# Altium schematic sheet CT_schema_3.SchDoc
size 335 x 238 mm
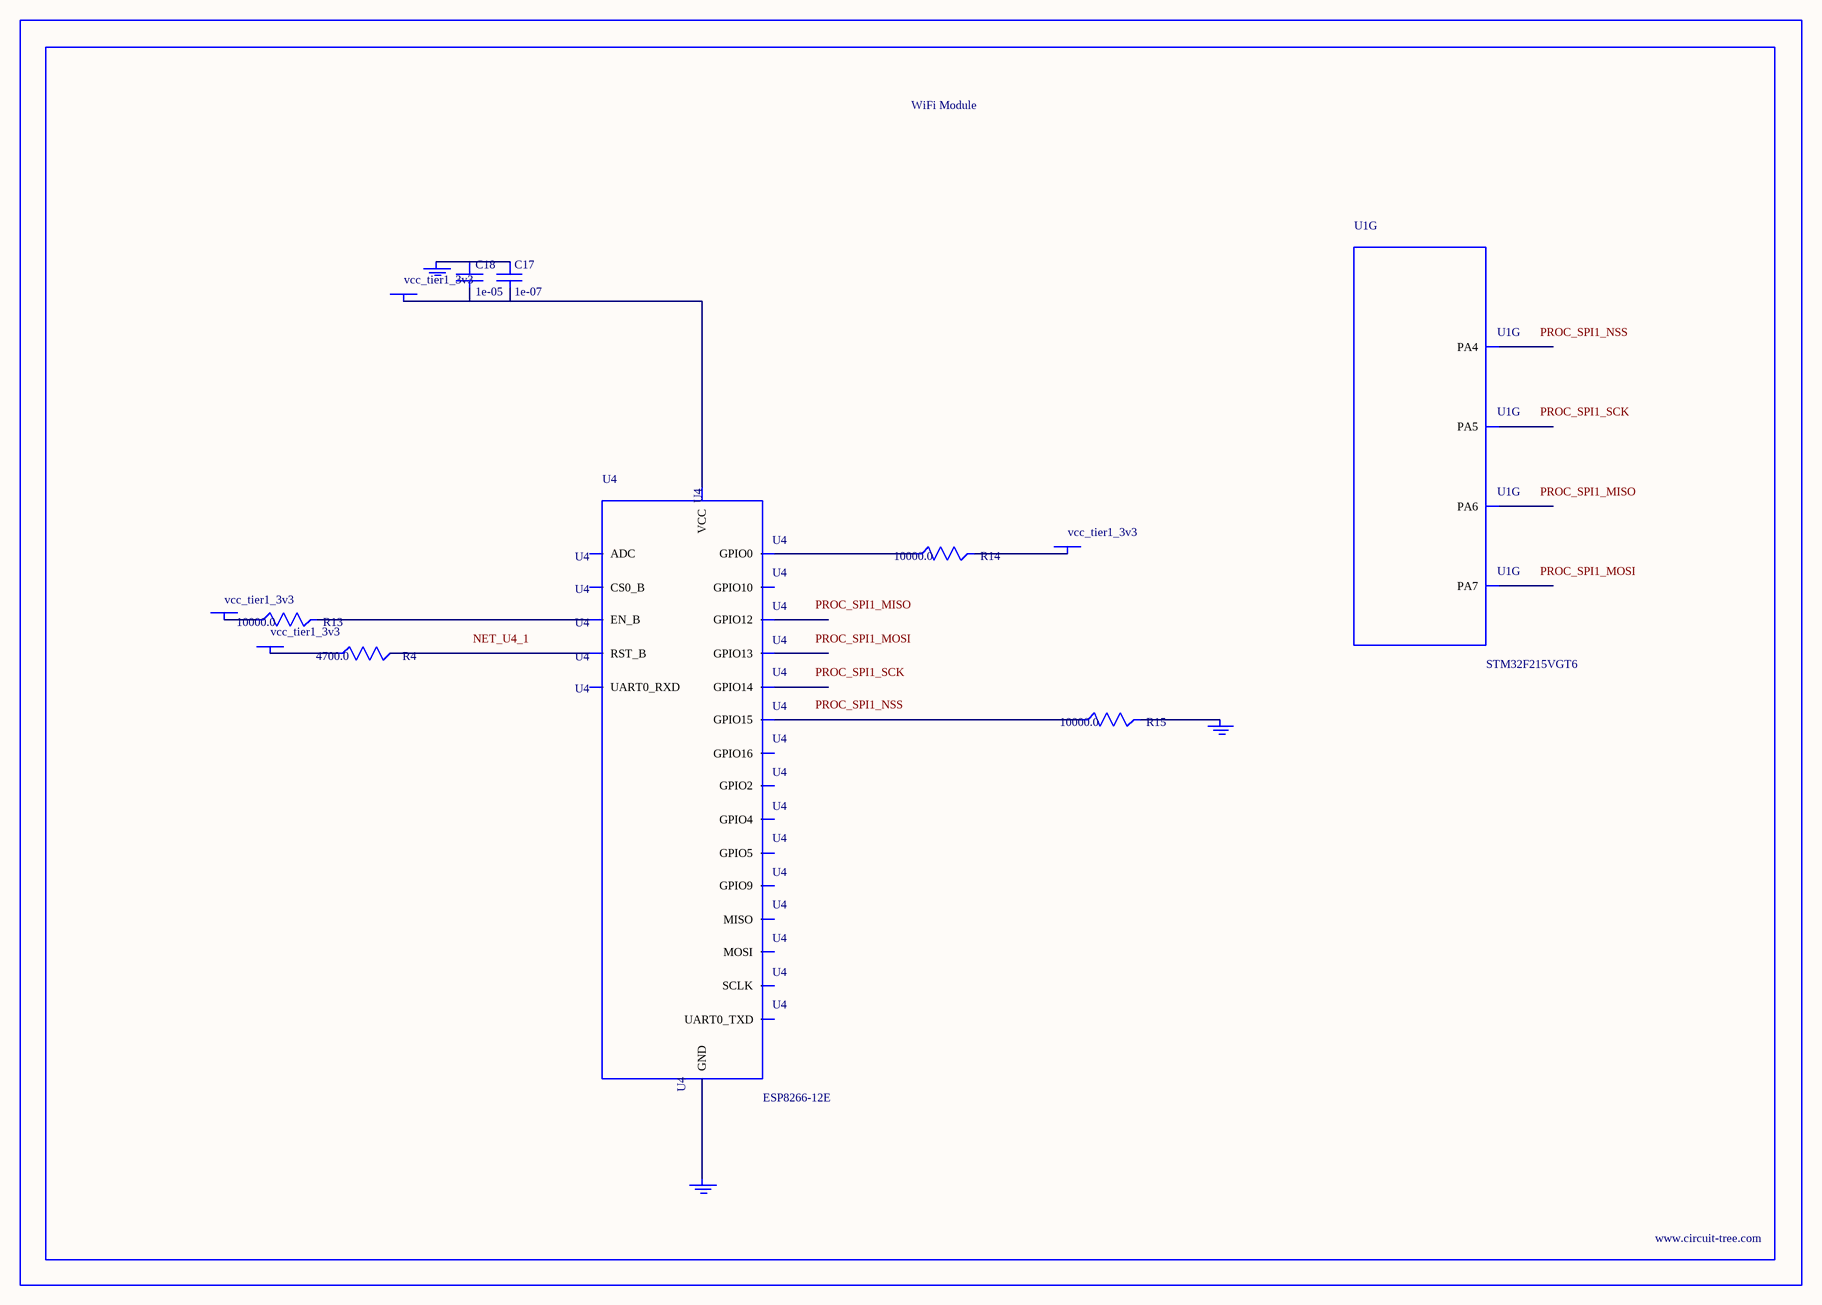
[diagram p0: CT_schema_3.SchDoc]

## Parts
BORDER2  (no value)
C17  1e-07  [C0402]
C18  1e-05  [C0805]
GND_INSTANCE_2_0  (no value)
GND_INSTANCE_2_1  (no value)
GND_INSTANCE_2_2  (no value)
POWER_INSTANCE_2_0  vcc_tier1_3v3
POWER_INSTANCE_2_1  vcc_tier1_3v3
POWER_INSTANCE_2_2  vcc_tier1_3v3
POWER_INSTANCE_2_3  vcc_tier1_3v3
R4  4700.0  [R0603]
R13  10000.0  [R0603]
R14  10000.0  [R0603]
R15  10000.0  [R0603]
U1  STM32F215VGT6  [LQFP100]  (part G of 10)
U4  ESP8266-12E  [ESP8266-12E]

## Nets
NetC17_1: C17.1 C18.1 GND_INSTANCE_2_0.0(GND)
NetC17_2: C17.2 C18.2 POWER_INSTANCE_2_1.0(PWR) U4.8(VCC)
NetGND_INSTANCE_2_1_0: GND_INSTANCE_2_1.0(GND) R15.2
NetGND_INSTANCE_2_2_0: GND_INSTANCE_2_2.0(GND) U4.15(GND)
NetPOWER_INSTANCE_2_0_0: POWER_INSTANCE_2_0.0(PWR) R13.1
NetPOWER_INSTANCE_2_2_0: POWER_INSTANCE_2_2.0(PWR) R14.2
NetPOWER_INSTANCE_2_3_0: POWER_INSTANCE_2_3.0(PWR) R4.1
NetR4_2: R4.2 U4.1(RST_B)
NetR13_2: R13.2 U4.3(EN_B)
NetR14_1: R14.1 U4.18(GPIO0)
NetR15_1: R15.1 U4.16(GPIO15)

Not connected (* = marked no-connect by the designer): U1 29(PA4) 30(PA5) 31(PA6) 32(PA7); U4 2(ADC) 4(GPIO16) 5(GPIO14) 6(GPIO12) 7(GPIO13) 9(CS0_B) 10(MISO) 11(GPIO9) 12(GPIO10) 13(MOSI) 14(SCLK) 17(GPIO2) 19(GPIO4) 20(GPIO5) 21(UART0_RXD) 22(UART0_TXD)

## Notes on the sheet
- Labels drawn without touching a wire or pin: NET_U4_1, PROC_SPI1_MISO, PROC_SPI1_MOSI, PROC_SPI1_NSS, PROC_SPI1_SCK

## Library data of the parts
BORDER2 = BORDER_PAGE2
C17 = C0402C104K3RACTU
C18 = C0805C106K8RACTU
GND_INSTANCE_2_0-GND_INSTANCE_2_2 = GND
POWER_INSTANCE_2_0-POWER_INSTANCE_2_3 = PWR
R4 = RC0603JR-074K7L
R13-R15 = RC0603JR-0710KL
